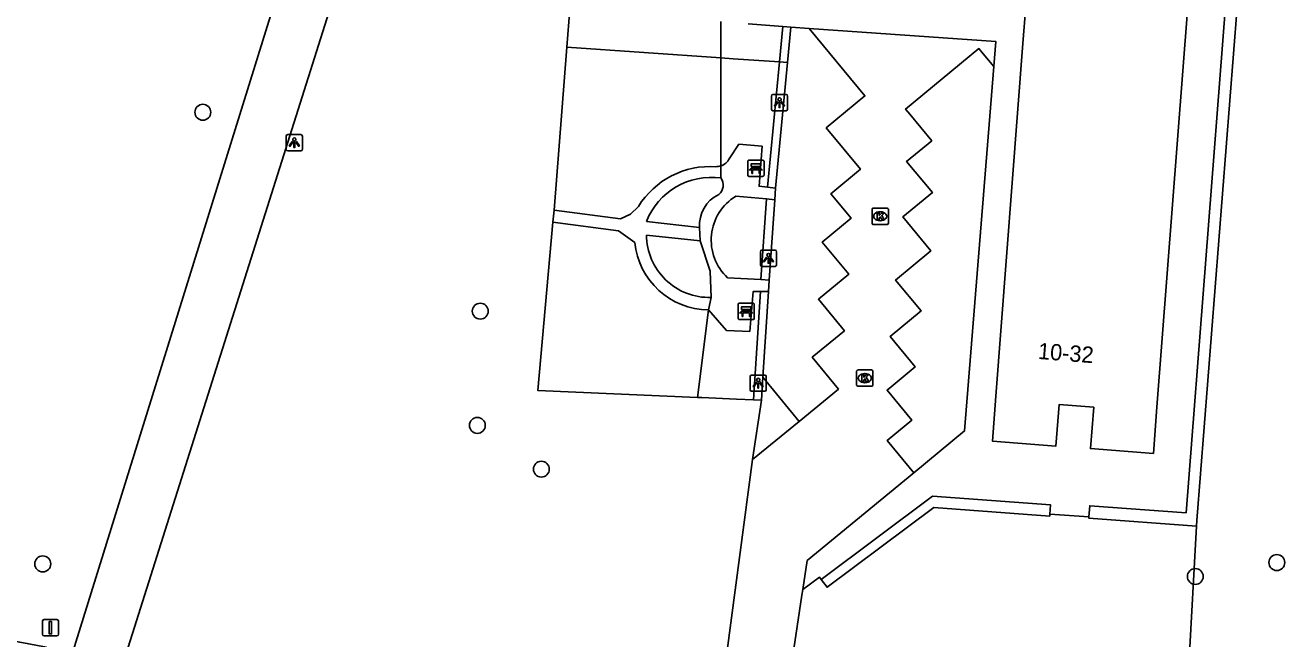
# Model space of a CAD drawing. Extents: x 161402 to 161933, y 381650 to 382313.
# Drawn here: x 161587.5 to 161664.9, y 381711.1 to 381748.8 of the extents above; entities that cross this region are included whole.
import ezdxf

# ---------------------------------------------------------------- set-up
doc = ezdxf.new("R2010")
doc.units = 0
for name, color, linetype in [('IMGEO_Bank', 7, 'Continuous'), ('IMGEO_Boom', 7, 'Continuous'), ('IMGEO_Groenvoorziening', 7, 'Continuous'), ('IMGEO_Haag', 7, 'Continuous'), ('IMGEO_Hek', 7, 'Continuous'), ('IMGEO_Kolk', 7, 'Continuous'), ('IMGEO_Lichtpunt', 7, 'Continuous'), ('IMGEO_Pand', 7, 'Continuous'), ('IMGEO_Pand_nummerreeks', 7, 'Continuous'), ('IMGEO_Parkeervlak_open', 7, 'Continuous'), ('IMGEO_Rijbaan_lokaal_open', 7, 'Continuous'), ('IMGEO_Verkeersbordpaal', 7, 'Continuous'), ('IMGEO_Voetpad_gesloten', 7, 'Continuous'), ('IMGEO_Voetpad_open', 7, 'Continuous')]:
    doc.layers.add(name, color=color, linetype=linetype)

msp = doc.modelspace()

# ---------------------------------------------------------------- linework, layer by layer
at = {"layer": 'IMGEO_Bank'}
for p, q in [((161631.866, 381739.608), (161631.866, 381740.449)), ((161631.866, 381740.449), (161631.866, 381739.608)), ((161631.941, 381740.533), (161632.782, 381740.533)), ((161632.782, 381740.533), (161631.941, 381740.533)), ((161632.866, 381740.458), (161632.866, 381739.617)), ((161632.866, 381739.617), (161632.866, 381740.458)), ((161632.563, 381739.931), (161632.17, 381739.931)), ((161632.175, 381740.039), (161632.175, 381740.145)), ((161632.219, 381740.145), (161632.219, 381740.039)), ((161632.507, 381740.151), (161632.225, 381740.151)), ((161632.225, 381740.033), (161632.507, 381740.033)), ((161632.513, 381740.039), (161632.513, 381740.145)), ((161632.557, 381740.145), (161632.557, 381740.039)), ((161632.791, 381739.533), (161631.95, 381739.533)), ((161631.95, 381739.533), (161632.791, 381739.533)), ((161631.268, 381730.81), (161631.268, 381731.651)), ((161631.268, 381731.651), (161631.268, 381730.81)), ((161631.343, 381731.735), (161632.184, 381731.735)), ((161632.184, 381731.735), (161631.343, 381731.735)), ((161631.965, 381731.133), (161631.572, 381731.133)), ((161631.577, 381731.241), (161631.577, 381731.347)), ((161631.621, 381731.347), (161631.621, 381731.241)), ((161631.909, 381731.353), (161631.627, 381731.353)), ((161631.627, 381731.235), (161631.909, 381731.235)), ((161631.915, 381731.241), (161631.915, 381731.347)), ((161631.959, 381731.347), (161631.959, 381731.241)), ((161632.268, 381731.66), (161632.268, 381730.819)), ((161632.268, 381730.819), (161632.268, 381731.66)), ((161632.193, 381730.735), (161631.352, 381730.735)), ((161631.352, 381730.735), (161632.193, 381730.735))]:
    msp.add_line(p, q, dxfattribs=at)
for points in [[(161632.113, 381739.931), (161631.971, 381739.931), (161632.083, 381740.033), (161632.169, 381740.033)], [(161632.169, 381740.151), (161632.083, 381740.151), (161632.083, 381740.312), (161632.646, 381740.312), (161632.646, 381740.151), (161632.563, 381740.151)], [(161632.163, 381739.924), (161632.163, 381739.717), (161632.12, 381739.717), (161632.12, 381739.924)], [(161632.563, 381740.033), (161632.646, 381740.033), (161632.758, 381739.931), (161632.619, 381739.931)], [(161632.613, 381739.924), (161632.613, 381739.717), (161632.569, 381739.717), (161632.569, 381739.924)], [(161631.515, 381731.133), (161631.373, 381731.133), (161631.485, 381731.235), (161631.571, 381731.235)], [(161631.571, 381731.353), (161631.485, 381731.353), (161631.485, 381731.514), (161632.048, 381731.514), (161632.048, 381731.353), (161631.965, 381731.353)], [(161631.565, 381731.126), (161631.565, 381730.919), (161631.522, 381730.919), (161631.522, 381731.126)], [(161631.965, 381731.235), (161632.048, 381731.235), (161632.16, 381731.133), (161632.021, 381731.133)], [(161632.015, 381731.126), (161632.015, 381730.919), (161631.971, 381730.919), (161631.971, 381731.126)]]:
    msp.add_lwpolyline(points, dxfattribs=at)
for centre, radius, start, end in [((161631.944, 381740.455), 0.0779, 92.4484, 184.28452), ((161631.944, 381740.455), 0.0779, 92.4484, 184.28452), ((161632.788, 381740.455), 0.0779, 2.4484, 94.28452), ((161632.788, 381740.455), 0.0779, 2.4484, 94.28452), ((161631.944, 381739.611), 0.0779, 182.4484, 274.28452), ((161631.944, 381739.611), 0.0779, 182.4484, 274.28452), ((161632.113, 381739.924), 0.00671, 2.89567, 87.10433), ((161632.17, 381739.924), 0.00671, 92.89567, 177.10433), ((161632.168, 381740.144), 0.00671, 2.89567, 87.10433), ((161632.168, 381740.04), 0.00671, 272.89567, 357.10433), ((161632.225, 381740.144), 0.00671, 92.89567, 177.10433), ((161632.225, 381740.04), 0.00671, 182.89567, 267.10433), ((161632.507, 381740.144), 0.00671, 2.89567, 87.10433), ((161632.507, 381740.04), 0.00671, 272.89567, 357.10433), ((161632.564, 381740.144), 0.00671, 92.89567, 177.10433), ((161632.564, 381740.04), 0.00671, 182.89567, 267.10433), ((161632.562, 381739.924), 0.00671, 2.89567, 87.10433), ((161632.619, 381739.924), 0.00671, 92.89567, 177.10433), ((161632.788, 381739.611), 0.0779, 272.4484, 4.28452), ((161632.788, 381739.611), 0.0779, 272.4484, 4.28452), ((161631.346, 381731.657), 0.0779, 92.4484, 184.28452), ((161631.346, 381731.657), 0.0779, 92.4484, 184.28452), ((161631.515, 381731.126), 0.00671, 2.89567, 87.10433), ((161631.572, 381731.126), 0.00671, 92.89567, 177.10433), ((161631.57, 381731.346), 0.00671, 2.89567, 87.10433), ((161631.57, 381731.242), 0.00671, 272.89567, 357.10433), ((161631.627, 381731.346), 0.00671, 92.89567, 177.10433), ((161631.627, 381731.242), 0.00671, 182.89567, 267.10433), ((161631.909, 381731.346), 0.00671, 2.89567, 87.10433), ((161631.909, 381731.242), 0.00671, 272.89567, 357.10433), ((161631.966, 381731.346), 0.00671, 92.89567, 177.10433), ((161631.966, 381731.242), 0.00671, 182.89567, 267.10433), ((161631.964, 381731.126), 0.00671, 2.89567, 87.10433), ((161632.021, 381731.126), 0.00671, 92.89567, 177.10433), ((161632.19, 381731.657), 0.0779, 2.4484, 94.28452), ((161632.19, 381731.657), 0.0779, 2.4484, 94.28452), ((161631.346, 381730.813), 0.0779, 182.4484, 274.28452), ((161631.346, 381730.813), 0.0779, 182.4484, 274.28452), ((161632.19, 381730.813), 0.0779, 272.4484, 4.28452), ((161632.19, 381730.813), 0.0779, 272.4484, 4.28452)]:
    msp.add_arc(centre, radius, start, end, dxfattribs=at)
at = {"layer": 'IMGEO_Boom'}
for centre in [(161598.377, 381743.475), (161615.428, 381731.244), (161615.249, 381724.221), (161619.18, 381721.53), (161588.542, 381715.703), (161664.377, 381715.786), (161659.366, 381714.93)]:
    msp.add_circle(centre, 0.489, dxfattribs=at)
at = {"layer": 'IMGEO_Groenvoorziening'}
for points in [[(161620.756, 381747.469), (161621.922, 381762.295), (161629.207, 381767.096)], [(161630.203, 381749.059), (161630.207, 381746.819)], [(161619.968, 381737.446), (161620.756, 381747.469)], [(161630.207, 381746.819), (161620.756, 381747.469)], [(161630.207, 381746.819), (161630.967, 381746.766), (161633.805, 381746.571)], [(161630.207, 381746.819), (161630.218, 381740.179)], [(161628.771, 381725.94), (161618.968, 381726.363), (161619.878, 381736.709)], [(161628.771, 381725.94), (161629.458, 381731.326)], [(161632.208, 381725.787), (161631.169, 381725.836), (161629.04, 381725.928), (161628.771, 381725.94)], [(161659.442, 381718.025), (161658.506, 381700.881)]]:
    msp.add_lwpolyline(points, dxfattribs=at)
at = {"layer": 'IMGEO_Haag'}
for points in [[(161659.442, 381718.025), (161659.461, 381718.372), (161661.941, 381749.945), (161662.713, 381760.042)], [(161633.805, 381746.571), (161634.01, 381748.744)], [(161633.805, 381746.571), (161633.077, 381738.869)], [(161634.304, 381746.537), (161633.805, 381746.571)], [(161632.678, 381733.185), (161633.026, 381738.144)], [(161632.641, 381732.452), (161632.208, 381725.787)], [(161632.708, 381725.764), (161632.208, 381725.787)], [(161650.433, 381718.759), (161650.424, 381718.643), (161643.3, 381719.172), (161636.738, 381714.264), (161636.381, 381714.742)], [(161652.831, 381718.594), (161652.825, 381718.515), (161659.442, 381718.025)]]:
    msp.add_lwpolyline(points, dxfattribs=at)
at = {"layer": 'IMGEO_Hek'}
for points in [[(161630.207, 381746.819), (161620.756, 381747.469)], [(161630.967, 381746.766), (161630.207, 381746.819)], [(161633.805, 381746.571), (161630.967, 381746.766)], [(161634.304, 381746.537), (161633.805, 381746.571)]]:
    msp.add_lwpolyline(points, dxfattribs=at)
at = {"layer": 'IMGEO_Kolk'}
for p, q in [((161639.503, 381736.655), (161639.503, 381737.507)), ((161639.578, 381737.581), (161640.43, 381737.581)), ((161639.991, 381737.361), (161640.016, 381737.361)), ((161640.504, 381737.507), (161640.504, 381736.655)), ((161640.43, 381736.581), (161639.578, 381736.581)), ((161640.014, 381736.801), (161639.989, 381736.801)), ((161638.556, 381726.702), (161638.556, 381727.554)), ((161638.631, 381727.628), (161639.483, 381727.628)), ((161639.044, 381727.408), (161639.069, 381727.408)), ((161639.557, 381727.554), (161639.557, 381726.702)), ((161639.483, 381726.628), (161638.631, 381726.628)), ((161639.067, 381726.848), (161639.042, 381726.848))]:
    msp.add_line(p, q, dxfattribs=at)
for points in [[(161639.503, 381736.655), (161639.503, 381737.507)], [(161639.578, 381737.581), (161640.43, 381737.581)], [(161639.824, 381737.281), (161639.947, 381737.281), (161639.947, 381737.13), (161640.077, 381737.281), (161640.241, 381737.281), (161640.095, 381737.13), (161640.248, 381736.881), (161640.096, 381736.881), (161640.011, 381737.045), (161639.947, 381736.978), (161639.947, 381736.881), (161639.824, 381736.881), (161639.824, 381737.281)], [(161640.504, 381737.507), (161640.504, 381736.655)], [(161640.43, 381736.581), (161639.578, 381736.581)], [(161638.556, 381726.702), (161638.556, 381727.554)], [(161638.631, 381727.628), (161639.483, 381727.628)], [(161638.877, 381727.328), (161639, 381727.328), (161639, 381727.177), (161639.13, 381727.328), (161639.294, 381727.328), (161639.148, 381727.177), (161639.301, 381726.928), (161639.149, 381726.928), (161639.064, 381727.092), (161639, 381727.025), (161639, 381726.928), (161638.877, 381726.928), (161638.877, 381727.328)], [(161639.557, 381727.554), (161639.557, 381726.702)], [(161639.483, 381726.628), (161638.631, 381726.628)]]:
    msp.add_lwpolyline(points, dxfattribs=at)
for centre, start, end in [((161639.58, 381737.505), 91.55205, 178.44795), ((161639.58, 381737.505), 91.55205, 178.44795), ((161640.428, 381737.505), 1.55205, 88.44795), ((161640.428, 381737.505), 1.55205, 88.44795), ((161639.58, 381736.657), 181.55205, 268.44795), ((161639.58, 381736.657), 181.55205, 268.44795), ((161640.428, 381736.657), 271.55205, 358.44795), ((161640.428, 381736.657), 271.55205, 358.44795), ((161638.633, 381727.552), 91.55205, 178.44795), ((161638.633, 381727.552), 91.55205, 178.44795), ((161639.481, 381727.552), 1.55205, 88.44795), ((161639.481, 381727.552), 1.55205, 88.44795), ((161638.633, 381726.704), 181.55205, 268.44795), ((161638.633, 381726.704), 181.55205, 268.44795), ((161639.481, 381726.704), 271.55205, 358.44795), ((161639.481, 381726.704), 271.55205, 358.44795)]:
    msp.add_arc(centre, 0.0765, start, end, dxfattribs=at)
for centre, major_axis, ratio, start_param, end_param in [((161639.99, 381737.081), (-0.387, 0.002), 0.722429, 4.712389, 7.853982), ((161640.015, 381737.081), (-0.39, 0.002), 0.717154, 1.570796, 4.712389), ((161639.043, 381727.128), (-0.387, 0.002), 0.722429, 4.712389, 7.853982), ((161639.068, 381727.128), (-0.39, 0.002), 0.717154, 1.570796, 4.712389)]:
    msp.add_ellipse(centre, major_axis=major_axis, ratio=ratio, start_param=start_param, end_param=end_param, dxfattribs=at)
at = {"layer": 'IMGEO_Lichtpunt'}
for p, q in [((161633.318, 381744.472), (161633.318, 381743.665)), ((161633.318, 381744.472), (161633.318, 381743.665)), ((161634.22, 381744.567), (161633.412, 381744.567)), ((161634.22, 381744.567), (161633.412, 381744.567)), ((161634.314, 381743.665), (161634.314, 381744.472)), ((161634.314, 381743.665), (161634.314, 381744.472)), ((161633.412, 381743.571), (161634.22, 381743.571)), ((161633.412, 381743.571), (161634.22, 381743.571)), ((161603.503, 381742.006), (161603.503, 381741.199)), ((161603.503, 381742.006), (161603.503, 381741.199)), ((161604.405, 381742.101), (161603.597, 381742.101)), ((161604.405, 381742.101), (161603.597, 381742.101)), ((161604.499, 381741.199), (161604.499, 381742.006)), ((161604.499, 381741.199), (161604.499, 381742.006)), ((161603.597, 381741.105), (161604.405, 381741.105)), ((161603.597, 381741.105), (161604.405, 381741.105)), ((161633.541, 381734.997), (161632.733, 381734.997)), ((161633.541, 381734.997), (161632.733, 381734.997)), ((161632.639, 381734.902), (161632.639, 381734.095)), ((161632.639, 381734.902), (161632.639, 381734.095)), ((161633.635, 381734.095), (161633.635, 381734.902)), ((161633.635, 381734.095), (161633.635, 381734.902)), ((161632.733, 381734.001), (161633.541, 381734.001)), ((161632.733, 381734.001), (161633.541, 381734.001)), ((161632.008, 381727.219), (161632.008, 381726.412)), ((161632.008, 381727.219), (161632.008, 381726.412)), ((161632.91, 381727.314), (161632.102, 381727.314)), ((161632.91, 381727.314), (161632.102, 381727.314)), ((161633.004, 381726.412), (161633.004, 381727.219)), ((161633.004, 381726.412), (161633.004, 381727.219)), ((161632.102, 381726.318), (161632.91, 381726.318)), ((161632.102, 381726.318), (161632.91, 381726.318))]:
    msp.add_line(p, q, dxfattribs=at)
for points in [[(161633.692, 381744.136), (161633.731, 381744.108), (161633.543, 381743.846), (161633.505, 381743.873), (161633.692, 381744.136)], [(161633.794, 381744.088), (161633.841, 381744.088), (161633.841, 381743.766), (161633.794, 381743.766), (161633.794, 381744.088)], [(161633.904, 381744.108), (161633.942, 381744.135), (161634.129, 381743.873), (161634.09, 381743.845), (161633.904, 381744.108)], [(161603.877, 381741.67), (161603.916, 381741.642), (161603.728, 381741.38), (161603.69, 381741.407), (161603.877, 381741.67)], [(161603.979, 381741.622), (161604.026, 381741.622), (161604.026, 381741.3), (161603.979, 381741.3), (161603.979, 381741.622)], [(161604.089, 381741.642), (161604.127, 381741.669), (161604.314, 381741.407), (161604.275, 381741.379), (161604.089, 381741.642)], [(161633.013, 381734.566), (161633.052, 381734.538), (161632.864, 381734.276), (161632.826, 381734.303), (161633.013, 381734.566)], [(161633.115, 381734.518), (161633.162, 381734.518), (161633.162, 381734.196), (161633.115, 381734.196), (161633.115, 381734.518)], [(161633.225, 381734.538), (161633.263, 381734.565), (161633.45, 381734.303), (161633.411, 381734.275), (161633.225, 381734.538)], [(161632.382, 381726.883), (161632.421, 381726.855), (161632.233, 381726.593), (161632.195, 381726.62), (161632.382, 381726.883)], [(161632.484, 381726.835), (161632.531, 381726.835), (161632.531, 381726.513), (161632.484, 381726.513), (161632.484, 381726.835)], [(161632.594, 381726.855), (161632.632, 381726.882), (161632.819, 381726.62), (161632.78, 381726.592), (161632.594, 381726.855)]]:
    msp.add_lwpolyline(points, dxfattribs=at)
for centre in [(161633.817, 381744.27), (161604.002, 381741.804), (161633.138, 381734.7), (161632.507, 381727.017)]:
    msp.add_circle(centre, 0.0994, dxfattribs=at)
for centre, start, end in [((161633.412, 381744.472), 90, 180), ((161633.412, 381744.472), 90, 180), ((161634.22, 381744.472), 0, 90), ((161634.22, 381744.472), 0, 90), ((161633.412, 381743.665), 180, 270), ((161633.412, 381743.665), 180, 270), ((161634.22, 381743.665), 270, 0), ((161634.22, 381743.665), 270, 360), ((161603.597, 381742.006), 90, 180), ((161603.597, 381742.006), 90, 180), ((161604.405, 381742.006), 0, 90), ((161604.405, 381742.006), 0, 90), ((161603.597, 381741.199), 180, 270), ((161603.597, 381741.199), 180, 270), ((161604.405, 381741.199), 270, 0), ((161604.405, 381741.199), 270, 360), ((161632.733, 381734.902), 90, 180), ((161632.733, 381734.902), 90, 180), ((161633.541, 381734.902), 0, 90), ((161633.541, 381734.902), 0, 90), ((161632.733, 381734.095), 180, 270), ((161632.733, 381734.095), 180, 270), ((161633.541, 381734.095), 270, 0), ((161633.541, 381734.095), 270, 360), ((161632.102, 381727.219), 90, 180), ((161632.102, 381727.219), 90, 180), ((161632.91, 381727.219), 0, 90), ((161632.91, 381727.219), 0, 90), ((161632.102, 381726.412), 180, 270), ((161632.102, 381726.412), 180, 270), ((161632.91, 381726.412), 270, 0), ((161632.91, 381726.412), 270, 360)]:
    msp.add_arc(centre, 0.0946, start, end, dxfattribs=at)
at = {"layer": 'IMGEO_Pand'}
msp.add_lwpolyline([(161658.913, 381750), (161657.001, 381725.343), (161656.794, 381722.493), (161652.926, 381722.793), (161653.123, 381725.334), (161650.997, 381725.499), (161650.799, 381722.944), (161646.904, 381723.247), (161647.117, 381726.028), (161648.778, 381747.713), (161648.953, 381750)], dxfattribs=at)
at = {"layer": 'IMGEO_Parkeervlak_open'}
for points in [[(161634.509, 381748.703), (161634.304, 381746.537)], [(161634.304, 381746.537), (161633.575, 381738.817)], [(161633.524, 381738.097), (161633.177, 381733.156)], [(161633.142, 381732.449), (161632.8, 381727.185)]]:
    msp.add_lwpolyline(points, dxfattribs=at)
at = {"layer": 'IMGEO_Rijbaan_lokaal_open'}
for points in [[(161635.642, 381748.624), (161639.068, 381744.479), (161636.689, 381742.513), (161638.791, 381739.97), (161636.972, 381738.467), (161638.216, 381736.962), (161636.443, 381735.498), (161638.077, 381733.521), (161636.204, 381731.973), (161637.8, 381730.041), (161635.824, 381728.407), (161637.435, 381726.458), (161635.02, 381724.462)], [(161635.642, 381748.624), (161647.106, 381747.829), (161646.983, 381746.288)], [(161642.06, 381721.305), (161640.427, 381723.282), (161641.957, 381724.546), (161640.427, 381726.397), (161642.15, 381727.821), (161640.607, 381729.687), (161642.512, 381731.261), (161640.946, 381733.156), (161643.114, 381734.948), (161641.388, 381737.037), (161643.209, 381738.541), (161641.627, 381740.455), (161643.169, 381741.729), (161641.829, 381743.351), (161641.565, 381743.67), (161646.07, 381747.393), (161646.334, 381747.073), (161646.983, 381746.288)], [(161635.02, 381724.462), (161632.151, 381722.118)], [(161630.603, 381710.376), (161632.151, 381722.118)], [(161642.06, 381721.305), (161635.507, 381715.911), (161635.242, 381714.132)], [(161635.242, 381714.132), (161635.188, 381713.771), (161633.775, 381704.284)]]:
    msp.add_lwpolyline(points, dxfattribs=at)
at = {"layer": 'IMGEO_Verkeersbordpaal'}
for p, q in [((161588.519, 381711.377), (161588.519, 381712.177)), ((161588.519, 381712.177), (161588.519, 381711.377)), ((161588.619, 381712.277), (161589.409, 381712.277)), ((161589.409, 381712.277), (161588.619, 381712.277)), ((161589.509, 381712.177), (161589.509, 381711.377)), ((161589.509, 381711.377), (161589.509, 381712.177)), ((161589.409, 381711.277), (161588.619, 381711.277)), ((161588.619, 381711.277), (161589.409, 381711.277))]:
    msp.add_line(p, q, dxfattribs=at)
msp.add_lwpolyline([(161588.939, 381712.152), (161589.089, 381712.152), (161589.089, 381711.402), (161588.939, 381711.402), (161588.939, 381712.152)], dxfattribs=at)
for centre, start, end in [((161588.619, 381712.177), 90, 180), ((161588.619, 381712.177), 90, 180), ((161589.409, 381712.177), 0, 90), ((161589.409, 381712.177), 360, 90), ((161588.619, 381711.377), 180, 270), ((161588.619, 381711.377), 180, 270), ((161589.409, 381711.377), 270, 0), ((161589.409, 381711.377), 270, 0)]:
    msp.add_arc(centre, 0.1, start, end, dxfattribs=at)
at = {"layer": 'IMGEO_Voetpad_gesloten'}
for points in [[(161593.549, 381709.799), (161606.251, 381750), (161622.439, 381801.233)], [(161618.166, 381798.995), (161602.713, 381750), (161590.391, 381710.295)]]:
    msp.add_lwpolyline(points, dxfattribs=at)
at = {"layer": 'IMGEO_Voetpad_open'}
for points in [[(161662.012, 381760.054), (161661.227, 381750), (161658.796, 381718.845), (161652.885, 381719.282), (161652.831, 381718.594)], [(161631.893, 381748.919), (161634.01, 381748.744)], [(161634.01, 381748.744), (161634.509, 381748.703)], [(161634.509, 381748.703), (161635.642, 381748.624)], [(161646.983, 381746.288), (161645.186, 381723.878), (161642.06, 381721.305)], [(161633.077, 381738.869), (161632.564, 381738.922), (161632.748, 381741.385), (161631.321, 381741.506), (161630.731, 381740.617)], [(161630.219, 381739.435), (161630.218, 381740.179)], [(161633.077, 381738.869), (161633.575, 381738.817)], [(161633.575, 381738.817), (161633.524, 381738.097)], [(161631.134, 381738.322), (161633.026, 381738.144)], [(161633.026, 381738.144), (161633.524, 381738.097)], [(161619.878, 381736.709), (161619.968, 381737.446)], [(161625.145, 381737.685), (161624.661, 381737.206), (161624.039, 381736.932), (161619.968, 381737.446)], [(161619.878, 381736.709), (161623.917, 381736.185), (161624.931, 381735.468)], [(161628.902, 381736.38), (161625.635, 381736.767)], [(161625.64, 381735.928), (161628.935, 381735.57)], [(161628.935, 381735.57), (161628.902, 381736.38)], [(161628.935, 381735.57), (161629.564, 381733.696), (161629.611, 381732.088)], [(161632.678, 381733.185), (161630.617, 381733.304)], [(161633.177, 381733.156), (161632.678, 381733.185)], [(161633.177, 381733.156), (161633.142, 381732.449)], [(161629.458, 381731.326), (161630.552, 381730.063), (161631.991, 381729.995), (161632.191, 381732.454), (161632.641, 381732.452)], [(161629.458, 381731.326), (161629.611, 381732.088)], [(161633.142, 381732.449), (161632.641, 381732.452)], [(161632.8, 381727.185), (161632.708, 381725.764)], [(161635.02, 381724.462), (161632.8, 381727.185)], [(161632.151, 381722.118), (161632.708, 381725.764)], [(161636.381, 381714.742), (161643.225, 381719.866), (161650.477, 381719.329), (161650.433, 381718.759)], [(161650.433, 381718.759), (161652.831, 381718.594)], [(161635.242, 381714.132), (161636.265, 381714.897), (161636.381, 381714.742)]]:
    msp.add_lwpolyline(points, dxfattribs=at)
for centre, radius, start, end in [((161629.92, 381741.047), 0.918, 288.93213, 332.04935), ((161629.553, 381734.955), 5.185, 86.02348, 148.23538), ((161629.912, 381741.073), 0.945, 270.07116, 288.91441), ((161629.644, 381735.151), 4.322, 82.35266, 158.04824), ((161629.626, 381739.001), 0.735, 308.0568, 36.20596), ((161631.014, 381736.523), 2.117, 116.20928, 183.87279), ((161632.793, 381735.615), 3.174, 121.49947, 226.73578), ((161629.508, 381735.954), 3.868, 180.39129, 271.53037), ((161629.486, 381735.902), 4.576, 185.4366, 269.64919), ((161655.59, 382082.843), 378.208, 257.13711, 259.8235)]:
    msp.add_arc(centre, radius, start, end, dxfattribs=at)

# ---------------------------------------------------------------- texts
at = {"layer": 'IMGEO_Pand_nummerreeks'}
msp.add_text('10-32', height=1, rotation=355.55958, dxfattribs=at).set_placement((161649.67, 381728.31))

doc.saveas('drawing.dxf')
